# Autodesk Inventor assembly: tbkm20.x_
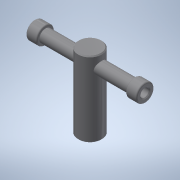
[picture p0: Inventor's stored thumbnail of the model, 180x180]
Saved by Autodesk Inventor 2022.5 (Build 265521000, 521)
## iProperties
Part Number: tbkm20.x_
Material: 一般
Document SubType Name: Assembly
Designer: ImaoCorp
Sending System: SOLIDWORKS 2017-2017317
MC: AMD64
MC_MODEL: Intel64 Family 6 Model 60 Stepping 3, GenuineIntel
OS: Windows_NT
FRU: Parasolid Version 29.0, build 201,  4-17-2017
FORMAT: text
GUISE: transmit
KEY: tbkm20
FILE: tbkm20.x_t
DATE: Wed Sep 18 16:34:42 2019
Author: ImaoCorp
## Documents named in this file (3)
- X:\14_SW2022-Inv2022\00_全2023-1023新製品(TCC)まで\t\tbkm20\TBKM20.iam
- X:\14_SW2022-Inv2022\00_全2023-1023新製品(TCC)まで\t\tbkm20\tbkm20_01.ipt
- X:\14_SW2022-Inv2022\00_全2023-1023新製品(TCC)まで\t\tbkm20\tbkm20_02.ipt
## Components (2 placed, 2 different names)
1. tbkm20_01
2. tbkm20_02
